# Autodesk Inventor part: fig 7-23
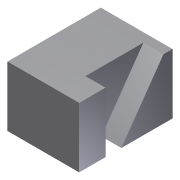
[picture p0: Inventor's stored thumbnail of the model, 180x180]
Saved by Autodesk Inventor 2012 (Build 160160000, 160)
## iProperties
Created: 2010-03
Part Number: fig 7-23
Document SubType Name: Modeling
Designer: CADSoft
Density: 1 g/cm^3
Material: Default
Author: CADSoft
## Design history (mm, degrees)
sketch "Sketch1"
  geometry: L1 (-16.027, 20.205)-(19.726, 20.205); L2 (19.726, 20.205)-(19.726, -26.37); L3 (19.726, -26.37)-(-16.027, -26.37); L4 (-16.027, -26.37)-(-16.027, 20.205); 1 further point
  constraints: 8 end point, 2 parallel, 1 horizontal, 1 perpendicular
extrude "Extrusion1" new body sketch "Sketch1" distance "d0" = 30; taper "d1" = 0 deg
sketch "Sketch2"
  geometry: L1 (-30, 46.575)-(-30, 0) reference; L2 (0, 46.575)-(0, 0) reference; L3 (-30, 13.159)-(0, 13.159); L4 (0, 13.159)-(0, 33.527); L5 (0, 33.527)-(-30, 33.527); L6 (-30, 33.527)-(-30, 13.159); 1 further point
  constraints: 8 end point, 2 parallel, 2 point on line, 1 horizontal, 1 perpendicular
extrude "Extrusion2" cut sketch "Sketch2" distance "d2" = 10; taper "d3" = 0 deg
feature "Move Face1"
feature "Move Face2"
body "Solid1"
